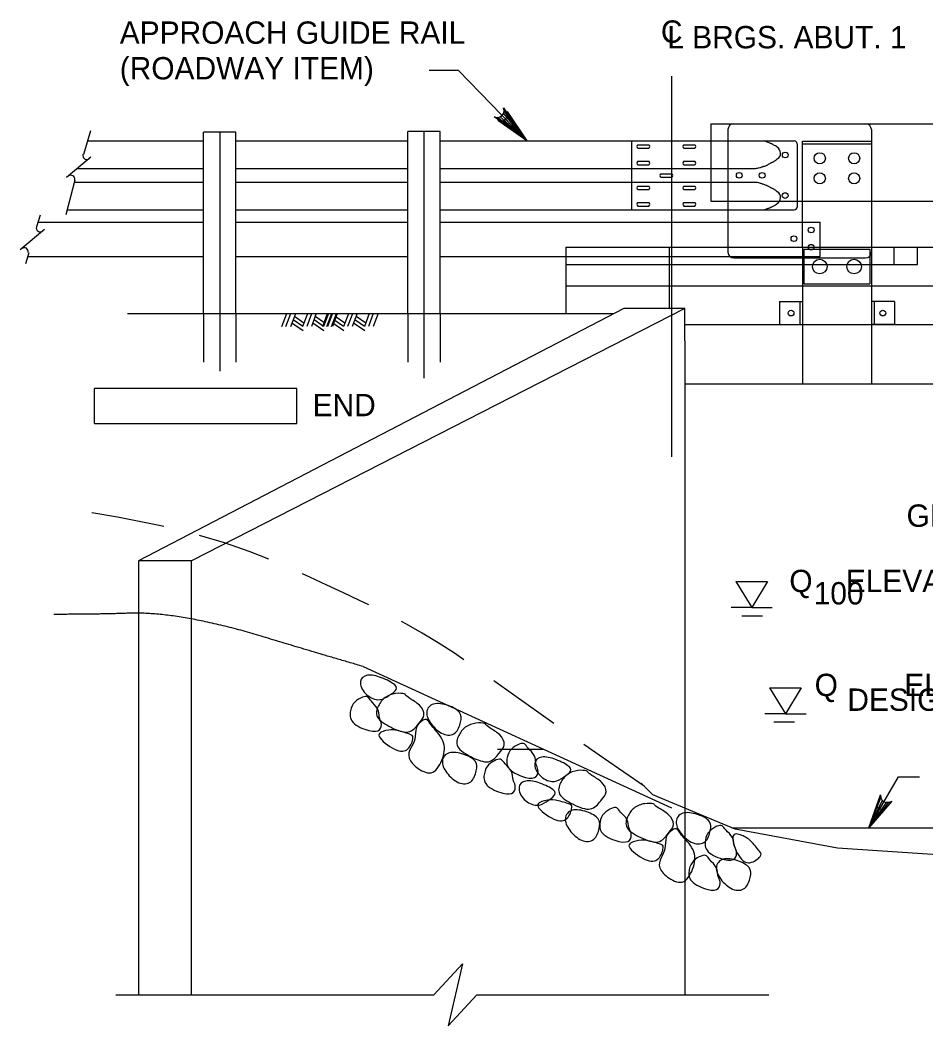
# Model space of a CAD drawing. Extents: x 638268 to 640277, y 295465 to 298435.
# Drawn here: x 638480.6 to 638602.1, y 296759.6 to 296894.5 of the extents above; entities that cross this region are included whole.
import ezdxf

# ---------------------------------------------------------------- set-up
doc = ezdxf.new("R2010")
doc.units = 0
for name, color, linetype in [('2', 7, 'Continuous'), ('3', 7, 'Continuous'), ('4', 7, 'Continuous'), ('52', 7, 'Continuous'), ('8', 7, 'Continuous'), ('Level 25', 7, 'Continuous')]:
    doc.layers.add(name, color=color, linetype=linetype)

msp = doc.modelspace()

# ---------------------------------------------------------------- linework, layer by layer
at = {"layer": '2'}
for p, q in [((638573.25, 296880.63), (638573.25, 296878.32)), ((638573.25, 296880.63), (638746.91, 296880.63)), ((638489.63, 296878.33), (638505.2, 296878.33)), ((638509.52, 296878.33), (638532.59, 296878.33)), ((638536.92, 296878.33), (638562.6, 296878.33)), ((638562.6, 296878.33), (638562.6, 296869.09)), ((638562.66, 296878.33), (638573.25, 296878.33)), ((638573.25, 296878.33), (638584.46, 296878.33)), ((638573.25, 296878.31), (638573.25, 296870.24)), ((638585.57, 296878.31), (638594.8, 296878.31)), ((638585.57, 296864.07), (638585.57, 296878.31)), ((638594.8, 296878.31), (638594.8, 296864.07)), ((638563.47, 296877.82), (638564.95, 296877.82)), ((638563.47, 296877.36), (638564.95, 296877.36)), ((638569.64, 296877.82), (638571.12, 296877.82)), ((638569.64, 296877.36), (638571.12, 296877.36)), ((638584.83, 296877.96), (638584.83, 296869.46)), ((638585.57, 296877.93), (638594.8, 296877.93)), ((638563.47, 296875.61), (638564.95, 296875.61)), ((638569.64, 296875.61), (638571.12, 296875.61)), ((638488.27, 296874.63), (638505.2, 296874.63)), ((638509.52, 296874.63), (638532.59, 296874.63)), ((638536.92, 296874.63), (638573.25, 296874.63)), ((638563.47, 296875.14), (638564.95, 296875.14)), ((638569.64, 296875.14), (638571.12, 296875.14)), ((638573.25, 296874.63), (638579, 296874.63)), ((638487.83, 296872.79), (638505.2, 296872.79)), ((638509.52, 296872.79), (638532.59, 296872.79)), ((638536.92, 296872.79), (638573.25, 296872.79)), ((638566.55, 296873.94), (638568.03, 296873.94)), ((638566.55, 296873.48), (638568.03, 296873.48)), ((638573.25, 296872.79), (638579, 296872.79)), ((638563.47, 296872.28), (638564.95, 296872.28)), ((638563.47, 296871.82), (638564.95, 296871.82)), ((638569.64, 296872.28), (638571.12, 296872.28)), ((638569.64, 296871.82), (638571.12, 296871.82)), ((638563.47, 296870.06), (638564.95, 296870.06)), ((638569.64, 296870.06), (638571.12, 296870.06)), ((638573.25, 296870.24), (638575.56, 296870.24)), ((638575.56, 296870.24), (638585.57, 296870.24)), ((638585.57, 296870.24), (638594.8, 296870.24)), ((638594.8, 296870.24), (638631.87, 296870.24)), ((638486.9, 296869.09), (638505.2, 296869.09)), ((638509.52, 296869.09), (638532.59, 296869.09)), ((638536.92, 296869.09), (638575.56, 296869.09)), ((638563.47, 296869.6), (638564.95, 296869.6)), ((638569.64, 296869.6), (638571.12, 296869.6)), ((638575.56, 296869.09), (638584.46, 296869.09)), ((638482.97, 296867.43), (638505.2, 296867.43)), ((638509.52, 296867.43), (638532.59, 296867.43)), ((638536.92, 296867.43), (638575.56, 296867.43)), ((638575.56, 296867.43), (638587.92, 296867.43)), ((638587.92, 296862.81), (638587.92, 296867.43)), ((638553.82, 296864.07), (638585.57, 296864.07)), ((638553.82, 296864.07), (638553.82, 296855.13)), ((638567.67, 296864.07), (638567.67, 296855.85)), ((638585.57, 296864.07), (638594.8, 296864.07)), ((638585.57, 296864.07), (638585.57, 296845.75)), ((638585.73, 296863.79), (638585.73, 296859.17)), ((638585.73, 296863.79), (638594.61, 296863.79)), ((638594.61, 296863.79), (638594.61, 296859.17)), ((638594.8, 296864.07), (638631.87, 296864.07)), ((638594.8, 296864.07), (638594.8, 296845.75)), ((638597.88, 296861.77), (638597.88, 296864.07)), ((638600.97, 296861.77), (638600.97, 296864.07)), ((638481.58, 296862.81), (638505.2, 296862.81)), ((638509.52, 296862.81), (638532.59, 296862.81)), ((638536.92, 296862.81), (638553.82, 296862.81)), ((638553.82, 296862.81), (638587.92, 296862.81)), ((638553.82, 296861.77), (638600.97, 296861.77)), ((638585.73, 296859.17), (638594.61, 296859.17)), ((638553.82, 296858.88), (638585.57, 296858.88)), ((638585.57, 296858.88), (638594.8, 296858.88)), ((638594.8, 296858.88), (638610.96, 296858.88)), ((638582.48, 296856.78), (638585.57, 296856.78)), ((638582.48, 296856.78), (638582.48, 296853.68)), ((638585.2, 296856.78), (638585.2, 296853.68)), ((638585.57, 296856.78), (638585.57, 296853.68)), ((638597.89, 296856.78), (638594.8, 296856.78)), ((638594.8, 296856.78), (638594.8, 296853.68)), ((638595.17, 296856.78), (638595.17, 296853.68)), ((638597.89, 296856.78), (638597.89, 296853.68)), ((638582.48, 296853.68), (638585.57, 296853.68)), ((638585.57, 296853.68), (638594.8, 296853.68)), ((638597.89, 296853.68), (638594.8, 296853.68))]:
    msp.add_line(p, q, dxfattribs=at)
for centre, radius in [((638583.25, 296876.45), 0.385), ((638587.88, 296876.01), 0.748), ((638592.49, 296876.01), 0.748), ((638577.07, 296873.72), 0.385), ((638580.15, 296873.72), 0.385), ((638587.88, 296873.31), 0.748), ((638592.49, 296873.31), 0.748), ((638583.23, 296871), 0.385), ((638586.72, 296866.38), 0.385), ((638584.41, 296865.22), 0.385), ((638586.72, 296864.07), 0.385), ((638587.88, 296861.47), 0.978), ((638592.49, 296861.47), 0.978), ((638584.03, 296855.23), 0.385), ((638596.34, 296855.23), 0.385)]:
    msp.add_circle(centre, radius, dxfattribs=at)
for centre, radius, start, end in [((638577.42, 296868.61), 10.17, 71.5066, 72.9766), ((638580.05, 296876.46), 1.88, 68.0907, 71.5066), ((638556.6, 296818.16), 64.73, 67.6851, 68.0907), ((638584.46, 296877.96), 0.369, 0, 90), ((638563.61, 296877.59), 0.269, 120.8559, 239.1441), ((638564.81, 296877.59), 0.269, 300.8559, 59.1441), ((638569.78, 296877.59), 0.269, 120.8559, 239.1441), ((638570.98, 296877.59), 0.269, 300.8559, 59.1441), ((638578.93, 296872.55), 5.93, 66.3453, 67.6851), ((638580.34, 296875.77), 2.42, 63.4251, 66.3453), ((638567.19, 296849.49), 31.8, 62.6202, 63.4251), ((638581.38, 296876.88), 0.955, 54.6771, 62.6202), ((638579.38, 296874.06), 4.42, 50.9849, 54.6771), ((638581.7, 296876.7), 0.916, 301.3851, 59.6468), ((638563.61, 296875.37), 0.269, 120.8559, 239.1441), ((638564.81, 296875.37), 0.269, 300.8559, 59.1441), ((638569.78, 296875.37), 0.269, 120.8559, 239.1441), ((638570.98, 296875.37), 0.269, 300.8559, 59.1441), ((638641.7, 296764.37), 126.36, 118.4725, 118.565), ((638394.18, 297220.77), 392.83, 298.4725, 298.525), ((638581.26, 296876.58), 1.09, 298.525, 306.8818), ((638578.94, 296879.66), 4.94, 306.8818, 310.7993), ((638578.77, 296879.66), 5.03, 272.6429, 278.367), ((638579.19, 296876.82), 2.16, 278.367, 287.1115), ((638552.76, 296962.65), 91.96, 287.1115, 287.3611), ((638579.27, 296877.87), 3.14, 287.3611, 288.7111), ((638574.44, 296892.11), 18.18, 288.7111, 290.2329), ((638580.51, 296875.66), 0.644, 290.2329, 298.3215), ((638570.64, 296893.98), 21.45, 298.3215, 298.7501), ((638636.31, 296774.28), 115.08, 118.565, 118.7501), ((638566.69, 296873.71), 0.269, 120.8559, 239.1441), ((638567.89, 296873.71), 0.269, 300.8559, 59.1441), ((638578.77, 296867.76), 5.03, 81.633, 87.3571), ((638579.19, 296870.6), 2.16, 72.8885, 81.633), ((638552.76, 296784.78), 91.96, 72.6389, 72.8885), ((638563.61, 296872.05), 0.269, 120.8559, 239.1441), ((638564.81, 296872.05), 0.269, 300.8559, 59.1441), ((638569.78, 296872.05), 0.269, 120.8559, 239.1441), ((638570.98, 296872.05), 0.269, 300.8559, 59.1441), ((638579.27, 296869.55), 3.14, 71.2889, 72.6389), ((638574.44, 296855.31), 18.18, 69.7671, 71.2889), ((638580.51, 296871.76), 0.644, 61.6785, 69.7671), ((638570.64, 296853.44), 21.45, 61.2499, 61.6785), ((638636.31, 296973.15), 115.08, 241.2499, 241.435), ((638641.7, 296983.05), 126.36, 241.435, 241.5275), ((638394.18, 296526.66), 392.83, 61.475, 61.5275), ((638581.26, 296870.85), 1.09, 53.1182, 61.475), ((638578.94, 296867.77), 4.94, 49.2007, 53.1182), ((638581.7, 296870.72), 0.916, 300.3532, 58.6149), ((638563.61, 296869.83), 0.269, 120.8559, 239.1441), ((638564.81, 296869.83), 0.269, 300.8559, 59.1441), ((638569.78, 296869.83), 0.269, 120.8559, 239.1441), ((638570.98, 296869.83), 0.269, 300.8559, 59.1441), ((638577.42, 296878.82), 10.17, 287.0234, 288.4934), ((638580.05, 296870.96), 1.88, 288.4934, 291.9093), ((638556.6, 296929.26), 64.73, 291.9093, 292.3149), ((638578.93, 296874.87), 5.93, 292.3149, 293.6547), ((638580.34, 296871.65), 2.42, 293.6547, 296.5749), ((638567.19, 296897.93), 31.8, 296.5749, 297.3798), ((638581.38, 296870.54), 0.955, 297.3798, 305.3229), ((638579.38, 296873.37), 4.42, 305.3229, 309.0151), ((638584.46, 296869.46), 0.369, 270, 0)]:
    msp.add_arc(centre, radius, start, end, dxfattribs=at)
at = {"layer": '3'}
for p, q in [((638509.52, 296879.52), (638505.2, 296879.52)), ((638505.2, 296855.13), (638505.2, 296879.52)), ((638507.36, 296879.52), (638507.36, 296847.43)), ((638509.52, 296855.13), (638509.52, 296879.52)), ((638536.92, 296879.59), (638532.59, 296879.59)), ((638532.59, 296855.13), (638532.59, 296879.59)), ((638534.76, 296879.59), (638534.76, 296846.48)), ((638536.92, 296855.13), (638536.92, 296879.59)), ((638490.08, 296876.16), (638486.82, 296873.42)), ((638487.9, 296873.08), (638486.73, 296868.41)), ((638483.28, 296868.37), (638482.78, 296866.82)), ((638483.84, 296866.44), (638480.58, 296863.7)), ((638560.19, 296855.13), (638494.99, 296855.13)), ((638561.57, 296855.85), (638496.45, 296821.97)), ((638569.79, 296855.85), (638503.58, 296821.97)), ((638505.2, 296855.13), (638505.2, 296848.64)), ((638509.52, 296855.13), (638509.52, 296848.64)), ((638516.32, 296855.13), (638515.66, 296853.37)), ((638516.87, 296855.13), (638516.21, 296853.38)), ((638517.51, 296855.14), (638516.84, 296853.39)), ((638519.14, 296855.14), (638518.48, 296853.41)), ((638519.68, 296855.15), (638519.03, 296853.42)), ((638520.32, 296855.16), (638519.67, 296853.43)), ((638521.8, 296855.13), (638521.14, 296853.37)), ((638521.95, 296855.16), (638521.29, 296853.42)), ((638522.35, 296855.13), (638521.68, 296853.38)), ((638522.49, 296855.16), (638521.84, 296853.43)), ((638522.99, 296855.14), (638522.32, 296853.39)), ((638523.13, 296855.16), (638522.48, 296853.44)), ((638524.62, 296855.14), (638523.96, 296853.41)), ((638525.16, 296855.15), (638524.51, 296853.42)), ((638525.8, 296855.16), (638525.15, 296853.43)), ((638527.43, 296855.16), (638526.77, 296853.42)), ((638527.97, 296855.16), (638527.32, 296853.43)), ((638528.61, 296855.16), (638527.96, 296853.44)), ((638532.59, 296855.13), (638532.59, 296848.64)), ((638536.92, 296855.13), (638536.92, 296848.64)), ((638569.79, 296855.85), (638561.57, 296855.85)), ((638569.79, 296851.52), (638569.79, 296855.85)), ((638569.79, 296851.52), (638569.79, 296855.85)), ((638517.04, 296853.92), (638518.54, 296852.88)), ((638517.21, 296854.37), (638518.5, 296853.48)), ((638517.38, 296854.8), (638518.67, 296853.91)), ((638519.85, 296853.93), (638521.35, 296852.89)), ((638520.02, 296854.38), (638521.31, 296853.49)), ((638520.18, 296854.81), (638521.48, 296853.92)), ((638522.52, 296853.92), (638524.02, 296852.88)), ((638522.69, 296854.37), (638523.98, 296853.48)), ((638522.86, 296854.8), (638524.15, 296853.91)), ((638525.33, 296853.93), (638526.83, 296852.89)), ((638525.5, 296854.38), (638526.79, 296853.49)), ((638525.66, 296854.81), (638526.96, 296853.92)), ((638569.79, 296853.68), (638583.48, 296853.68)), ((638569.79, 296853.68), (638585.57, 296853.68)), ((638594.8, 296853.68), (638631.87, 296853.68)), ((638594.8, 296853.68), (638631.06, 296853.68)), ((638569.79, 296851.52), (638569.79, 296788.79)), ((638569.79, 296845.75), (638748.57, 296845.75)), ((638569.79, 296845.75), (638748.57, 296845.75)), ((638503.58, 296821.97), (638496.45, 296821.97)), ((638496.45, 296821.97), (638496.45, 296814.85)), ((638503.58, 296814.09), (638503.58, 296821.97)), ((638496.45, 296814.85), (638496.45, 296763.74)), ((638503.58, 296763.74), (638503.58, 296814.09)), ((638526.61, 296807.8), (638567.98, 296788.82)), ((638544.63, 296796.73), (638550.73, 296796.73)), ((638569.79, 296788.79), (638569.79, 296763.74)), ((638576.14, 296786.13), (638736.87, 296786.13)), ((638536.09, 296763.74), (638539.93, 296767.92)), ((638539.93, 296767.92), (638538.01, 296759.57)), ((638493.41, 296763.74), (638536.09, 296763.74)), ((638538.01, 296759.57), (638541.85, 296763.74)), ((638541.85, 296763.74), (638581.05, 296763.74))]:
    msp.add_line(p, q, dxfattribs=at)
for centre, start, end in [((638489.52, 296876.38), 162.1496, 312.1496), ((638487.38, 296873.2), 347.4782, 130.0168), ((638487.38, 296873.19), 130.0028, 130.0168), ((638483.28, 296866.66), 162.1496, 312.1496), ((638481.14, 296863.47), 347.4782, 130.0168), ((638481.14, 296863.47), 130.0028, 130.0168)]:
    msp.add_arc(centre, 0.533, start, end, dxfattribs=at)
for points, degree in [([(638526.61, 296807.8), (638518.08, 296810.29), (638508.15, 296813.34), (638498.62, 296815.09), (638491.28, 296814.8), (638485.12, 296814.8)], 2), ([(638530.89, 296804.53), (638530.65, 296804.27), (638529.78, 296803.72), (638528.68, 296803.08), (638526.7, 296804.02), (638525.94, 296805.94), (638527.03, 296806.85), (638529.05, 296806.41), (638531.23, 296805.27), (638531.14, 296804.79), (638530.89, 296804.53)], 3), ([(638532.31, 296803.97), (638532.36, 296803.89), (638532.69, 296803.6), (638534.28, 296802.69), (638535.07, 296801.25), (638534.07, 296800.2), (638532.87, 296798.58), (638530.29, 296799.58), (638528.07, 296800.99), (638528.62, 296802.59), (638529.41, 296803.71), (638531.01, 296804.32), (638532.36, 296804.11), (638532.25, 296804.06), (638532.31, 296803.97)], 3), ([(638528.77, 296801.03), (638528.84, 296800.73), (638529.14, 296800.37), (638528.99, 296799.14), (638527.65, 296798.97), (638524.75, 296800.22), (638524.85, 296801.98), (638525.36, 296803.08), (638526.62, 296803.79), (638527.27, 296803.82), (638527.57, 296803.2), (638528.75, 296802.17), (638528.71, 296801.33), (638528.77, 296801.03)], 3), ([(638539.53, 296801.64), (638539.81, 296801.26), (638539.77, 296800.43), (638539.15, 296798.6), (638537.31, 296798.47), (638535.56, 296800.09), (638534.86, 296801.72), (638535.83, 296803.06), (638538.1, 296802.65), (638539.26, 296802.01), (638539.53, 296801.64)], 3), ([(638535.21, 296800.67), (638535.35, 296800.58), (638535.46, 296800.12), (638537.72, 296797.81), (638537.47, 296795.6), (638536.08, 296793.01), (638533.88, 296794.02), (638532.47, 296795.53), (638532.94, 296796.9), (638533.69, 296797.92), (638533.54, 296799.76), (638534.63, 296800.66), (638535.07, 296800.76), (638535.21, 296800.67)], 3), ([(638543.08, 296799.99), (638543.14, 296799.91), (638543.47, 296799.62), (638545.06, 296798.7), (638545.85, 296797.27), (638544.85, 296796.22), (638543.64, 296794.59), (638541.07, 296795.6), (638538.85, 296797.01), (638539.39, 296798.61), (638540.18, 296799.73), (638541.78, 296800.34), (638543.13, 296800.13), (638543.03, 296800.08), (638543.08, 296799.99)], 3), ([(638532.76, 296798.75), (638533.18, 296798.6), (638533.49, 296798.5), (638532.78, 296796.44), (638531.06, 296796.27), (638527.94, 296798.74), (638529.78, 296799.26), (638530.97, 296799.37), (638532.34, 296798.89), (638532.76, 296798.75)], 3), ([(638549.8, 296794.74), (638549.86, 296794.44), (638550.17, 296794.07), (638550.01, 296792.85), (638548.67, 296792.68), (638545.78, 296793.93), (638545.87, 296795.69), (638546.38, 296796.79), (638547.64, 296797.49), (638548.3, 296797.52), (638548.6, 296796.91), (638549.77, 296795.88), (638549.73, 296795.04), (638549.8, 296794.74)], 3), ([(638541.64, 296795.09), (638541.92, 296794.71), (638541.88, 296793.88), (638541.25, 296792.05), (638539.41, 296791.92), (638537.66, 296793.54), (638536.96, 296795.17), (638537.93, 296796.51), (638540.2, 296796.1), (638541.36, 296795.46), (638541.64, 296795.09)], 3), ([(638554.28, 296793.55), (638554.04, 296793.29), (638553.17, 296792.74), (638552.07, 296792.1), (638550.09, 296793.03), (638549.33, 296794.96), (638550.42, 296795.87), (638552.44, 296795.43), (638554.62, 296794.29), (638554.52, 296793.81), (638554.28, 296793.55)], 3), ([(638546.73, 296792.62), (638546.8, 296792.32), (638547.1, 296791.95), (638546.95, 296790.73), (638545.6, 296790.56), (638542.71, 296791.81), (638542.8, 296793.57), (638543.32, 296794.67), (638544.58, 296795.37), (638545.23, 296795.4), (638545.53, 296794.79), (638546.7, 296793.76), (638546.66, 296792.92), (638546.73, 296792.62)], 3), ([(638556.75, 296793.64), (638556.8, 296793.55), (638557.13, 296793.27), (638558.72, 296792.35), (638559.52, 296790.92), (638558.51, 296789.87), (638557.31, 296788.24), (638554.73, 296789.24), (638552.51, 296790.65), (638553.06, 296792.25), (638553.85, 296793.37), (638555.45, 296793.98), (638556.8, 296793.77), (638556.69, 296793.72), (638556.75, 296793.64)], 3), ([(638552.2, 296790.43), (638551.97, 296790.17), (638551.11, 296789.59), (638550.02, 296788.92), (638548.02, 296789.8), (638547.21, 296791.72), (638548.27, 296792.65), (638550.31, 296792.26), (638552.51, 296791.18), (638552.43, 296790.69), (638552.2, 296790.43)], 3), ([(638554.06, 296789.42), (638554.48, 296789.29), (638554.79, 296789.19), (638554.14, 296787.12), (638552.42, 296786.9), (638549.24, 296789.28), (638551.07, 296789.85), (638552.25, 296789.99), (638553.64, 296789.55), (638554.06, 296789.42)], 3), ([(638565.72, 296789.22), (638565.78, 296789.14), (638566.12, 296788.86), (638567.73, 296787.98), (638568.56, 296786.57), (638567.58, 296785.5), (638566.42, 296783.84), (638563.82, 296784.77), (638561.56, 296786.13), (638562.07, 296787.74), (638562.83, 296788.88), (638564.42, 296789.53), (638565.77, 296789.36), (638565.66, 296789.3), (638565.72, 296789.22)], 3), ([(638558.13, 296787.37), (638558.41, 296787), (638558.37, 296786.16), (638557.75, 296784.33), (638555.9, 296784.2), (638554.16, 296785.82), (638553.46, 296787.46), (638554.43, 296788.79), (638556.7, 296788.39), (638557.85, 296787.74), (638558.13, 296787.37)], 3), ([(638562.27, 296786.19), (638562.34, 296785.89), (638562.65, 296785.53), (638562.53, 296784.3), (638561.19, 296784.1), (638558.27, 296785.27), (638558.32, 296787.03), (638558.8, 296788.14), (638560.04, 296788.88), (638560.7, 296788.93), (638561.01, 296788.33), (638562.21, 296787.33), (638562.19, 296786.49), (638562.27, 296786.19)], 3), ([(638573.01, 296787.07), (638573.3, 296786.7), (638573.28, 296785.87), (638572.7, 296784.02), (638570.86, 296783.84), (638569.07, 296785.42), (638568.33, 296787.03), (638569.27, 296788.39), (638571.55, 296788.05), (638572.72, 296787.43), (638573.01, 296787.07)], 3), ([(638576.4, 296783.77), (638576.48, 296783.47), (638576.79, 296783.11), (638576.67, 296781.88), (638575.33, 296781.68), (638572.41, 296782.85), (638572.45, 296784.61), (638572.94, 296785.73), (638574.18, 296786.47), (638574.83, 296786.51), (638575.15, 296785.91), (638576.35, 296784.91), (638576.33, 296784.07), (638576.4, 296783.77)], 3), ([(638568.71, 296785.99), (638568.85, 296785.9), (638568.98, 296785.45), (638571.3, 296783.2), (638571.11, 296780.98), (638569.77, 296778.36), (638567.55, 296779.31), (638566.1, 296780.78), (638566.53, 296782.17), (638567.26, 296783.2), (638567.07, 296785.04), (638568.13, 296785.97), (638568.57, 296786.07), (638568.71, 296785.99)], 3), ([(638579.74, 296783.05), (638580.01, 296782.7), (638580.21, 296782.45), (638578.48, 296781.12), (638576.95, 296781.92), (638575.71, 296785.7), (638577.54, 296785.13), (638578.58, 296784.55), (638579.47, 296783.4), (638579.74, 296783.05)], 3), ([(638566.31, 296784.01), (638566.74, 296783.87), (638567.04, 296783.78), (638566.39, 296781.7), (638564.67, 296781.48), (638561.49, 296783.87), (638563.32, 296784.44), (638564.51, 296784.58), (638565.89, 296784.14), (638566.31, 296784.01)], 3), ([(638574.22, 296779.72), (638574.29, 296779.42), (638574.59, 296779.05), (638574.44, 296777.83), (638573.1, 296777.66), (638570.2, 296778.91), (638570.3, 296780.67), (638570.81, 296781.77), (638572.07, 296782.48), (638572.72, 296782.51), (638573.02, 296781.89), (638574.19, 296780.86), (638574.16, 296780.02), (638574.22, 296779.72)], 3), ([(638578.4, 296780.81), (638578.67, 296780.44), (638578.64, 296779.6), (638578.01, 296777.77), (638576.17, 296777.64), (638574.42, 296779.26), (638573.72, 296780.89), (638574.69, 296782.23), (638576.96, 296781.82), (638578.12, 296781.18), (638578.4, 296780.81)], 3)]:
    msp.add_open_spline(points, degree=degree, dxfattribs=at)
at = {"layer": '4'}
for p, q in [((638539.41, 296887.8), (638535.47, 296887.8)), ((638548.06, 296878.83), (638539.41, 296887.8)), ((638567.98, 296887.03), (638567.98, 296835.96)), ((638517.73, 296845.11), (638490.58, 296845.11)), ((638490.58, 296840.4), (638490.58, 296845.11)), ((638517.73, 296840.4), (638517.73, 296845.11)), ((638490.58, 296840.4), (638517.73, 296840.4)), ((638576.62, 296819.22), (638578.74, 296815.73)), ((638576.62, 296819.22), (638580.86, 296819.22)), ((638580.86, 296819.22), (638578.74, 296815.73)), ((638578.74, 296815.73), (638575.97, 296815.73)), ((638578.74, 296815.73), (638581.51, 296815.73)), ((638577.43, 296814.59), (638580.2, 296814.59)), ((638581.14, 296804.94), (638585.38, 296804.94)), ((638581.14, 296804.94), (638583.26, 296801.45)), ((638585.38, 296804.94), (638583.26, 296801.45)), ((638583.26, 296801.45), (638580.49, 296801.45)), ((638583.26, 296801.45), (638586.03, 296801.45)), ((638581.71, 296800.37), (638584.48, 296800.37)), ((638594.44, 296786.13), (638598.45, 296792.99)), ((638598.45, 296792.99), (638601.26, 296792.99))]:
    msp.add_line(p, q, dxfattribs=at)
for points in [[(638548.06, 296878.83), (638544.2, 296881.58), (638544.63, 296881.49), (638544.98, 296881.58), (638545.24, 296881.76), (638545.43, 296882.01), (638545.53, 296882.36), (638545.46, 296882.79), (638548.06, 296878.83), (638545.53, 296882.36), (638545.43, 296882.01), (638548.06, 296878.83), (638545.24, 296881.76), (638544.98, 296881.58), (638548.06, 296878.83), (638544.63, 296881.49)], [(638548.55, 296878.33), (638544.68, 296881.08), (638545.11, 296880.99), (638545.47, 296881.08), (638545.73, 296881.25), (638545.91, 296881.51), (638546.01, 296881.86), (638545.94, 296882.29), (638548.55, 296878.33), (638546.01, 296881.86), (638545.91, 296881.51), (638548.55, 296878.33), (638545.73, 296881.25), (638545.47, 296881.08), (638548.55, 296878.33), (638545.11, 296880.99)], [(638605.67, 296782.41), (638590.26, 296783.41), (638576.51, 296785.98), (638565.47, 296790.6), (638563.9, 296792.16)], [(638594.44, 296786.13), (638596.04, 296790.6), (638596.07, 296790.16), (638596.25, 296789.84), (638596.49, 296789.64), (638596.79, 296789.53), (638597.15, 296789.53), (638597.55, 296789.72), (638594.44, 296786.13), (638597.15, 296789.53), (638596.79, 296789.53), (638594.44, 296786.13), (638596.49, 296789.64), (638596.25, 296789.84), (638594.44, 296786.13), (638596.07, 296790.16)]]:
    msp.add_lwpolyline(points, dxfattribs=at)
msp.add_lwpolyline([(638595.55, 296788.98), (638596.37, 296788.49), (638594.5, 296786.25)], close=True, dxfattribs=at)
at = {"layer": '52'}
for p, q in [((638490.03, 296879.7), (638489.09, 296876.52)), ((638481.74, 296863.34), (638481.28, 296861.85))]:
    msp.add_line(p, q, dxfattribs=at)
at = {"layer": '8'}
for p, q in [((638493.66, 296827.85), (638490.19, 296828.41)), ((638499.24, 296826.73), (638493.66, 296827.85)), ((638499.85, 296826.58), (638499.24, 296826.73)), ((638508.01, 296824.39), (638504.63, 296825.38)), ((638511.45, 296823.2), (638508.01, 296824.39)), ((638513.94, 296822.22), (638511.45, 296823.2)), ((638519.45, 296819.77), (638518.45, 296820.24)), ((638521.75, 296818.72), (638519.45, 296819.77)), ((638523.96, 296817.69), (638521.75, 296818.72)), ((638526.12, 296816.68), (638523.96, 296817.69)), ((638527.37, 296816.08), (638526.12, 296816.68)), ((638532.42, 296813.48), (638531.75, 296813.84)), ((638534.52, 296812.29), (638532.42, 296813.48)), ((638536.66, 296810.99), (638534.52, 296812.29)), ((638538.85, 296809.57), (638536.66, 296810.99)), ((638540.13, 296808.69), (638538.85, 296809.57)), ((638546.76, 296804.02), (638544.16, 296805.87)), ((638550.19, 296801.58), (638546.76, 296804.02)), ((638552.19, 296800.17), (638550.19, 296801.58)), ((638558.86, 296795.49), (638556.21, 296797.34)), ((638564.31, 296791.75), (638558.86, 296795.49))]:
    msp.add_line(p, q, dxfattribs=at)
at = {"layer": 'Level 25'}
for p, q in [((638575.56, 296879.86), (638575.56, 296878.32)), ((638576.33, 296880.63), (638594.03, 296880.63)), ((638594.8, 296879.86), (638594.8, 296878.31)), ((638575.56, 296878.32), (638575.56, 296869.09)), ((638575.56, 296869.09), (638575.56, 296864.07)), ((638575.56, 296864.07), (638575.56, 296863.41)), ((638576.33, 296862.64), (638594.03, 296862.64))]:
    msp.add_line(p, q, dxfattribs=at)
for centre, start, end in [((638576.33, 296879.86), 90, 180), ((638594.03, 296879.86), 0, 90), ((638576.33, 296863.41), 180, 270), ((638594.03, 296863.41), 270, 0)]:
    msp.add_arc(centre, 0.77, start, end, dxfattribs=at)

# ---------------------------------------------------------------- texts
at = {"layer": '4'}
for s, p in [('APPROACH GUIDE RAIL', (638493.95, 296891.37)), ('C', (638566.56, 296891.51)), ('L BRGS. ABUT. 1', (638567.42, 296890.76)), ('(ROADWAY ITEM)', (638493.95, 296886.59)), ('END', (638519.83, 296841.39)), ('GLULAM STIFFENER BEAM (TYP.)', (638599.52, 296826.55)), ('Q    ELEVATION - ', (638583.79, 296817.78)), ('100', (638587.06, 296816.13)), ('Q        ELEVATION - ', (638587.19, 296803.83)), ('DESIGN', (638591.58, 296801.85))]:
    msp.add_text(s, height=3, dxfattribs=at).set_placement(p)

doc.saveas('drawing.dxf')
